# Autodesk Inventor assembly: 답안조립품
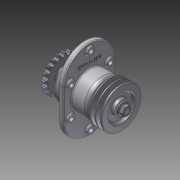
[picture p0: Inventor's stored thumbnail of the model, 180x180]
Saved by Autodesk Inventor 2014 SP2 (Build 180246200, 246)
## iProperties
Created: 2015-02
Part Number: 답안조립품
Document SubType Name: Assembly
Designer: 201-08
Author: 201-08
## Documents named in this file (12)
- C:\Users\201-08\Desktop\450207V1007\답안조립품.iam
- C:\Users\201-08\Desktop\450207V1007\본체.ipt
- C:\Users\201-08\Desktop\450207V1007\2-커버.ipt
- C:\Users\201-08\Desktop\450207V1007\3-축.ipt
- C:\Users\201-08\Desktop\450207V1007\4-V벨트풀리.ipt
- C:\Users\201-08\Desktop\450207V1007\5-체인 스프로킷.ipt
- C:\Users\201-08\Desktop\450207V1007\6-베어링 6206.ipt
- C:\Users\201-08\Desktop\450207V1007\7-부시.ipt
- C:\Users\201-08\Desktop\450207V1007\8-오일실 30x42.ipt
- C:\Users\201-08\Desktop\450207V1007\9-M16-너트.ipt
- C:\Users\201-08\Desktop\450207V1007\10-M6.ipt
- C:\Users\201-08\Desktop\450207V1007\11-키 6x6.ipt
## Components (22 placed, 10 different names)
1. 2-커버:1
2. 2-커버:2
3. 3-축:1 — 각도:1
4. 4-V벨트풀리:1 — 각도:2
5. 5-체인 스프로킷:1 — 각도:3
6. 6-베어링 6206:1
7. 6-베어링 6206:2
8. 7-부시:1
9. 8-8-오일실 30x42:1
10. 8-8-오일실 30x42:2
11. 9-M16 너트:1
12. 9-M16 너트:2
13. 11-키 6x6:1 — 각도:2
14. 11-키 6x6:2 — 각도:3
15. 10-M6:1
16. 10-M6:3
17. 10-M6:4
18. 10-M6:5
19. 10-M6:2
20. 10-M6:6
21. 10-M6:7
22. 10-M6:8
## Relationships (3: Angle 3)
- 각도:1 [Angle]: 3-축:1
- 각도:2 [Angle]: 4-V벨트풀리:1 ↔ 11-키 6x6:1
- 각도:3 [Angle]: 5-체인 스프로킷:1 ↔ 11-키 6x6:2
